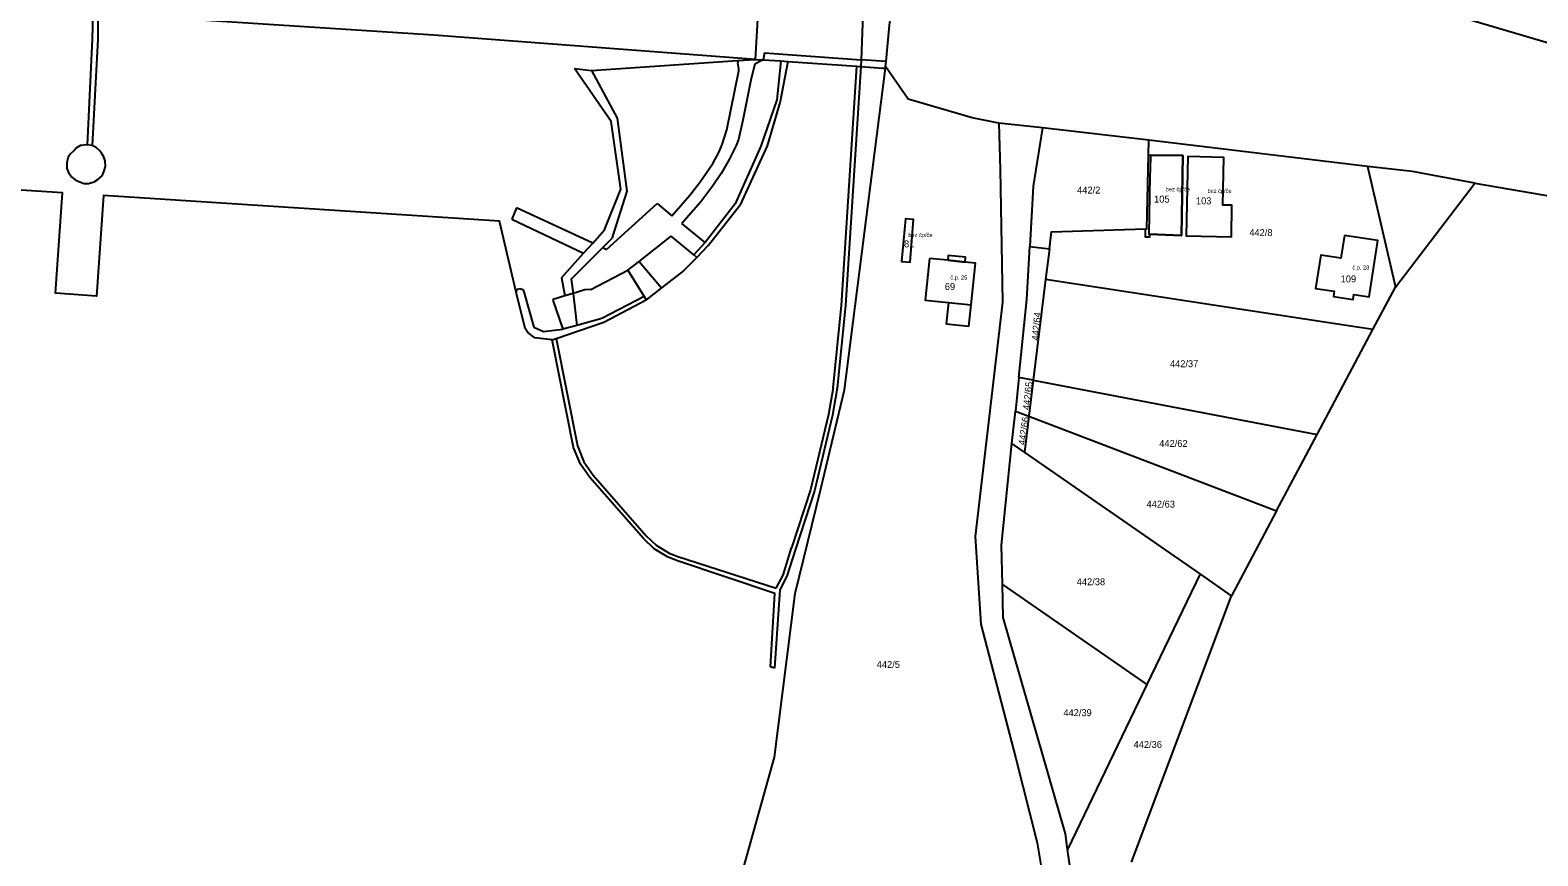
# Model space of a CAD drawing. Extents: x -887272 to -877616, y -1026687 to -1019819.
# Drawn here: x -880439.4 to -880069.6, y -1022775.2 to -1022572.6 of the extents above; entities that cross this region are included whole.
import ezdxf

# ---------------------------------------------------------------- set-up
doc = ezdxf.new("R2010")
doc.units = 0
for name, color, linetype in [('Definiční body', 7, 'Continuous'), ('Hranice parcel', 7, 'Continuous'), ('Parcelní čísla', 7, 'Continuous'), ('Polygon budovy', 7, 'Continuous'), ('Vnitřní kresba', 7, 'Continuous')]:
    doc.layers.add(name, color=color, linetype=linetype)

msp = doc.modelspace()

# ---------------------------------------------------------------- linework, layer by layer
at = {"layer": 'Hranice parcel'}
for p, q in [((-880229.65, -1022581.98), (-880229.6, -1022581.58)), ((-880229.65, -1022581.98), (-880229.6, -1022581.58)), ((-880191.14, -1022596.56), (-880201.85, -1022595.42)), ((-880165.02, -1022599.62), (-880191.14, -1022596.56)), ((-880165.11, -1022603.24), (-880165.02, -1022599.62)), ((-880165.11, -1022603.24), (-880164.68, -1022603.25)), ((-880194.24, -1022625.73), (-880189.45, -1022626.3)), ((-880189.45, -1022626.3), (-880190.36, -1022633.76)), ((-880190.36, -1022633.76), (-880193.39, -1022658.51)), ((-880123.76, -1022671.82), (-880110.08, -1022646.06)), ((-880196.94, -1022657.83), (-880197.79, -1022666.07)), ((-880193.39, -1022658.51), (-880196.94, -1022657.83)), ((-880193.39, -1022658.51), (-880194.47, -1022667.34)), ((-880193.39, -1022658.51), (-880123.76, -1022671.82)), ((-880198.62, -1022674.04), (-880197.79, -1022666.07)), ((-880197.79, -1022666.07), (-880194.47, -1022667.34)), ((-880194.47, -1022667.34), (-880195.55, -1022676.17)), ((-880194.47, -1022667.34), (-880133.71, -1022690.56)), ((-880133.71, -1022690.56), (-880123.76, -1022671.82)), ((-880195.55, -1022676.17), (-880198.62, -1022674.04)), ((-880152.45, -1022706.02), (-880195.55, -1022676.17)), ((-880133.71, -1022690.56), (-880144.75, -1022711.36)), ((-880200.98, -1022708.57), (-880165.51, -1022733.13)), ((-880152.45, -1022706.02), (-880165.51, -1022733.13)), ((-880144.75, -1022711.36), (-880152.45, -1022706.02)), ((-880169.29, -1022776.73), (-880144.75, -1022711.36)), ((-880165.51, -1022733.13), (-880184.98, -1022773.58))]:
    msp.add_line(p, q, dxfattribs=at)
for points in [[(-880166.5, -1022548.2), (-880166.5, -1022563), (-880091.71, -1022568.45), (-880004.96, -1022594.04), (-879942.81, -1022618.93)], [(-880235.23, -1022569.97), (-880235.27, -1022571.01), (-880235.62, -1022579.89), (-880235.68, -1022581.56)], [(-880229.6, -1022581.58), (-880229.48, -1022580.34), (-880228.62, -1022571.37), (-880228.52, -1022570.28)], [(-880229.6, -1022581.58), (-880229.48, -1022580.34), (-880228.62, -1022571.37), (-880228.52, -1022570.28)], [(-880256.89, -1022729.12), (-880257.82, -1022728.77), (-880256.81, -1022710.79), (-880280.91, -1022702.69), (-880283.09, -1022701.83), (-880286.4, -1022699.81), (-880289.01, -1022697.35), (-880302.11, -1022682.39), (-880304.45, -1022679.11), (-880306.13, -1022674.96), (-880311.39, -1022648.61), (-880315.62, -1022648.06), (-880317.36, -1022646.76), (-880318.04, -1022645.79), (-880320.19, -1022636.87), (-880324.31, -1022619.44), (-880421.4, -1022613.18), (-880423.11, -1022637.86), (-880433.18, -1022637.17), (-880431.48, -1022612.53), (-880889.2, -1022583.06)], [(-880275.46, -1022817.7), (-880256.82, -1022750.96), (-880251.78, -1022710.78), (-880245.5, -1022685.14), (-880239.72, -1022660.82), (-880229.65, -1022581.98)], [(-880275.46, -1022817.7), (-880256.82, -1022750.96), (-880251.78, -1022710.78), (-880245.5, -1022685.14), (-880239.72, -1022660.82), (-880229.65, -1022581.98)], [(-880235.68, -1022581.56), (-880239.44, -1022640.2), (-880241.51, -1022660.47), (-880242.64, -1022667.04), (-880247.06, -1022685.59), (-880251.71, -1022699.93), (-880253.82, -1022706.59)], [(-880201.85, -1022595.42), (-880208.37, -1022594.15), (-880224.11, -1022589.52), (-880229.6, -1022581.58)], [(-880201.85, -1022595.42), (-880201.5, -1022606.82), (-880200.91, -1022639.32), (-880207.63, -1022696.81), (-880206.25, -1022718.31), (-880197.77, -1022750.95), (-880192.42, -1022771.99), (-880190.9, -1022781.26)], [(-880191.14, -1022596.56), (-880193.43, -1022610.91), (-880194.24, -1022625.73)], [(-880085.09, -1022610.19), (-880100.38, -1022607.29), (-880111.43, -1022606.07), (-880165.02, -1022599.62)], [(-880165.85, -1022621.37), (-880165.55, -1022621.36), (-880165.11, -1022603.24)], [(-880164.68, -1022603.25), (-880156.7, -1022603.38), (-880157.02, -1022623.01), (-880164.89, -1022622.7)], [(-880146.89, -1022615.53), (-880146.62, -1022603.84), (-880155.47, -1022603.64), (-880155.91, -1022623.1), (-880144.81, -1022623.36), (-880144.66, -1022615.58), (-880146.89, -1022615.53)], [(-880110.08, -1022646.06), (-880104.57, -1022635.67), (-880085.09, -1022610.19)], [(-880085.09, -1022610.19), (-880006.95, -1022623.58), (-879948.33, -1022639.86), (-879895.51, -1022661.38), (-879854.76, -1022684.53)], [(-880223.61, -1022629.54), (-880222.73, -1022619.05), (-880224.76, -1022618.92), (-880225.68, -1022629.39), (-880223.61, -1022629.54)], [(-880189.45, -1022626.3), (-880188.93, -1022622.11), (-880165.85, -1022621.37)], [(-880164.89, -1022622.7), (-880164.92, -1022623.44), (-880165.89, -1022623.4), (-880165.85, -1022621.37)], [(-880117.08, -1022623.02), (-880117.95, -1022628.55), (-880122.9, -1022627.78), (-880124.2, -1022636.02), (-880119.61, -1022636.65), (-880119.79, -1022637.93), (-880114.95, -1022638.69), (-880114.75, -1022637.47), (-880111.03, -1022638.06), (-880108.92, -1022624.26), (-880117.08, -1022623.02)], [(-880218.86, -1022628.64), (-880219.91, -1022638.86), (-880214.19, -1022639.45), (-880214.73, -1022644.64), (-880209.18, -1022645.22), (-880208.64, -1022640.02), (-880207.57, -1022629.75), (-880210.12, -1022629.5), (-880210, -1022628.28), (-880214.26, -1022627.86), (-880214.38, -1022629.08), (-880218.86, -1022628.64)], [(-880196.94, -1022657.83), (-880194.95, -1022638.71), (-880194.24, -1022625.73)], [(-880110.08, -1022646.06), (-880119.83, -1022644.57), (-880190.36, -1022633.76)], [(-880200.98, -1022708.57), (-880201.21, -1022698.97), (-880198.62, -1022674.04)], [(-880253.82, -1022706.59), (-880255.54, -1022709.92), (-880256.89, -1022729.12)], [(-880184.98, -1022773.58), (-880185.52, -1022769.75), (-880200.78, -1022716.69), (-880200.98, -1022708.57)], [(-880183.96, -1022798.18), (-880184.04, -1022780.28), (-880184.98, -1022773.58)]]:
    msp.add_lwpolyline(points, dxfattribs=at)
at = {"layer": 'Polygon budovy'}
for points in [[(-880164.68, -1022603.25), (-880164.73, -1022606.78), (-880164.82, -1022608.39), (-880165.02, -1022622.7), (-880164.89, -1022622.7), (-880157.02, -1022623.01), (-880156.7, -1022603.38)], [(-880146.62, -1022603.84), (-880155.47, -1022603.64), (-880155.91, -1022623.1), (-880144.81, -1022623.36), (-880144.66, -1022615.58), (-880146.89, -1022615.53)], [(-880225.68, -1022629.39), (-880223.61, -1022629.54), (-880222.73, -1022619.05), (-880224.76, -1022618.92)], [(-880117.08, -1022623.02), (-880117.95, -1022628.55), (-880122.9, -1022627.78), (-880124.2, -1022636.02), (-880119.61, -1022636.65), (-880119.79, -1022637.93), (-880114.95, -1022638.69), (-880114.75, -1022637.47), (-880111.03, -1022638.06), (-880108.92, -1022624.26)], [(-880218.86, -1022628.64), (-880219.91, -1022638.86), (-880214.19, -1022639.45), (-880208.64, -1022640.02), (-880207.57, -1022629.75), (-880210.12, -1022629.5), (-880214.38, -1022629.08)]]:
    msp.add_lwpolyline(points, close=True, dxfattribs=at)
at = {"layer": 'Vnitřní kresba'}
for p, q in [((-880424, -1022568.5), (-880424.22, -1022574.8)), ((-880422.78, -1022568.56), (-880422.84, -1022574.82)), ((-880340.44, -1022573.88), (-880422.78, -1022568.56)), ((-880260.96, -1022568.52), (-880261.58, -1022579.8)), ((-880424.22, -1022574.8), (-880425.46, -1022600.76)), ((-880422.84, -1022574.82), (-880424.16, -1022600.94)), ((-880261.58, -1022579.8), (-880340.44, -1022573.88)), ((-880265.92, -1022580.11), (-880261.58, -1022579.8)), ((-880261.58, -1022579.8), (-880259.64, -1022579.92)), ((-880259.32, -1022578.16), (-880259.64, -1022579.92)), ((-880259.32, -1022578.16), (-880235.62, -1022579.89)), ((-880296.9, -1022595.02), (-880305.88, -1022582.02)), ((-880305.88, -1022582.02), (-880301.72, -1022582.52)), ((-880301.72, -1022582.52), (-880265.92, -1022580.11)), ((-880301.72, -1022582.52), (-880295.46, -1022594.18)), ((-880268.55, -1022597.08), (-880265.63, -1022582.63)), ((-880265.92, -1022580.11), (-880265.83, -1022580.66)), ((-880265.6, -1022582.14), (-880265.83, -1022580.66)), ((-880265.63, -1022582.63), (-880265.6, -1022582.14)), ((-880261.66, -1022580.98), (-880262.54, -1022584.5)), ((-880260.16, -1022580.19), (-880261.66, -1022580.98)), ((-880259.64, -1022579.92), (-880260.16, -1022580.19)), ((-880259.64, -1022579.92), (-880255.34, -1022580.18)), ((-880255.34, -1022580.18), (-880256.3, -1022589.68)), ((-880253.59, -1022580.3), (-880255.5, -1022590.14)), ((-880255.34, -1022580.18), (-880253.59, -1022580.3)), ((-880253.59, -1022580.3), (-880236.68, -1022581.5)), ((-880240.44, -1022640.14), (-880236.68, -1022581.5)), ((-880236.68, -1022581.5), (-880236.1, -1022581.54)), ((-880236.1, -1022581.54), (-880235.68, -1022581.56)), ((-880235.68, -1022581.56), (-880230.31, -1022581.93)), ((-880229.48, -1022580.34), (-880235.62, -1022579.89)), ((-880230.31, -1022581.93), (-880229.65, -1022581.98)), ((-880262.54, -1022584.5), (-880264.65, -1022594.7)), ((-880256.3, -1022589.68), (-880260.22, -1022601.12)), ((-880255.5, -1022590.14), (-880258.68, -1022600.96)), ((-880295.46, -1022594.18), (-880293.04, -1022612.08)), ((-880294.58, -1022611.66), (-880296.9, -1022595.02)), ((-880269.69, -1022600.68), (-880268.55, -1022597.08)), ((-880264.65, -1022594.7), (-880265.68, -1022599.47)), ((-880428.04, -1022601.52), (-880428.62, -1022602.12)), ((-880427.06, -1022600.92), (-880428.04, -1022601.52)), ((-880425.46, -1022600.76), (-880427.06, -1022600.92)), ((-880424.16, -1022600.94), (-880425.46, -1022600.76)), ((-880423.2, -1022601.44), (-880424.16, -1022600.94)), ((-880422.42, -1022602.14), (-880423.2, -1022601.44)), ((-880270.53, -1022602.6), (-880269.69, -1022600.68)), ((-880266.25, -1022600.93), (-880267.95, -1022604.37)), ((-880260.22, -1022601.12), (-880266.5, -1022615.24)), ((-880265.68, -1022599.47), (-880266.25, -1022600.93)), ((-880258.68, -1022600.96), (-880265.28, -1022615.5)), ((-880430.1, -1022603.78), (-880430.42, -1022605.08)), ((-880430.42, -1022605.08), (-880430.38, -1022606.52)), ((-880429.5, -1022602.94), (-880430.1, -1022603.78)), ((-880428.62, -1022602.12), (-880429.5, -1022602.94)), ((-880421.92, -1022602.8), (-880422.42, -1022602.14)), ((-880421.34, -1022603.72), (-880421.92, -1022602.8)), ((-880421.02, -1022604.7), (-880421.34, -1022603.72)), ((-880420.92, -1022606.04), (-880421.02, -1022604.7)), ((-880275.07, -1022609.82), (-880271.97, -1022605.32)), ((-880271.97, -1022605.32), (-880270.53, -1022602.6)), ((-880267.95, -1022604.37), (-880269.92, -1022607.76)), ((-880164.68, -1022603.25), (-880164.73, -1022606.78)), ((-880430.38, -1022606.52), (-880430, -1022607.52)), ((-880430, -1022607.52), (-880429.24, -1022608.64)), ((-880429.24, -1022608.64), (-880428.36, -1022609.32)), ((-880428.36, -1022609.32), (-880427.06, -1022609.94)), ((-880423.68, -1022609.8), (-880422.78, -1022609.24)), ((-880422.78, -1022609.24), (-880421.76, -1022608.38)), ((-880421.76, -1022608.38), (-880421.3, -1022607.38)), ((-880421.3, -1022607.38), (-880420.92, -1022606.04)), ((-880269.92, -1022607.76), (-880271.99, -1022610.85)), ((-880164.82, -1022608.39), (-880165.02, -1022622.7)), ((-880164.73, -1022606.78), (-880164.82, -1022608.39)), ((-880111.43, -1022606.07), (-880104.57, -1022635.67)), ((-880427.06, -1022609.94), (-880426.18, -1022610.26)), ((-880426.18, -1022610.26), (-880425.12, -1022610.26)), ((-880425.12, -1022610.26), (-880423.68, -1022609.8)), ((-880298.58, -1022621.64), (-880294.58, -1022611.66)), ((-880293.04, -1022612.08), (-880296.71, -1022623.71)), ((-880282.04, -1022618.16), (-880277.59, -1022613.1)), ((-880277.59, -1022613.1), (-880275.07, -1022609.82)), ((-880271.99, -1022610.85), (-880274.95, -1022614.76)), ((-880320.09, -1022616.22), (-880321.26, -1022618.95)), ((-880301.44, -1022624.84), (-880320.09, -1022616.22)), ((-880298.02, -1022626.42), (-880285.64, -1022615.16)), ((-880285.64, -1022615.16), (-880282.04, -1022618.16)), ((-880274.95, -1022614.76), (-880279.57, -1022620.06)), ((-880266.5, -1022615.24), (-880273.84, -1022624.71)), ((-880273.06, -1022625.34), (-880265.28, -1022615.5)), ((-880321.26, -1022618.95), (-880303.68, -1022627.34)), ((-880273.84, -1022624.71), (-880279.57, -1022620.06)), ((-880301.44, -1022624.84), (-880298.58, -1022621.64)), ((-880298.99, -1022625.97), (-880296.71, -1022623.71)), ((-880290.03, -1022629.41), (-880282.16, -1022623.14)), ((-880276.68, -1022627.73), (-880282.16, -1022623.14)), ((-880165.02, -1022622.7), (-880164.89, -1022622.7)), ((-880309.06, -1022633.34), (-880303.68, -1022627.34)), ((-880303.68, -1022627.34), (-880301.44, -1022624.84)), ((-880301.45, -1022628.4), (-880298.99, -1022625.97)), ((-880298.99, -1022625.97), (-880298.02, -1022626.42)), ((-880276.68, -1022627.73), (-880273.84, -1022624.71)), ((-880275.91, -1022628.37), (-880276.68, -1022627.73)), ((-880273.26, -1022625.6), (-880275.91, -1022628.37)), ((-880273.06, -1022625.34), (-880273.26, -1022625.6)), ((-880306.69, -1022633.69), (-880304.04, -1022631.01)), ((-880304.04, -1022631.01), (-880301.45, -1022628.4)), ((-880301.92, -1022636.26), (-880292.85, -1022631.5)), ((-880292.85, -1022631.5), (-880290.03, -1022629.41)), ((-880292.85, -1022631.5), (-880288.84, -1022637.95)), ((-880290.03, -1022629.41), (-880284.55, -1022635.82)), ((-880275.91, -1022628.37), (-880279.21, -1022631.65)), ((-880214.38, -1022629.08), (-880210.12, -1022629.5)), ((-880309.06, -1022633.34), (-880308.26, -1022637.82)), ((-880306.69, -1022633.69), (-880306.27, -1022637.21)), ((-880279.21, -1022631.65), (-880284.55, -1022635.82)), ((-880320.08, -1022636.27), (-880320.19, -1022636.87)), ((-880319.05, -1022636.08), (-880320.08, -1022636.27)), ((-880319.05, -1022636.08), (-880318.59, -1022636.27)), ((-880318.59, -1022636.27), (-880318.33, -1022636.83)), ((-880318.33, -1022636.83), (-880315.9, -1022645.45)), ((-880311.2, -1022638.85), (-880311.12, -1022638.68)), ((-880311.2, -1022638.85), (-880308.76, -1022645.98)), ((-880308.26, -1022637.82), (-880311.12, -1022638.68)), ((-880306.27, -1022637.21), (-880308.26, -1022637.82)), ((-880303.41, -1022636.35), (-880306.27, -1022637.21)), ((-880306.27, -1022637.21), (-880305.34, -1022645.04)), ((-880301.92, -1022636.26), (-880303.41, -1022636.35)), ((-880288.84, -1022637.95), (-880299.19, -1022643.35)), ((-880298.73, -1022644.24), (-880288.33, -1022638.77)), ((-880288.84, -1022637.95), (-880288.33, -1022638.77)), ((-880284.55, -1022635.82), (-880288.33, -1022638.77)), ((-880242.5, -1022660.37), (-880240.44, -1022640.14)), ((-880214.19, -1022639.45), (-880208.64, -1022640.02)), ((-880315.9, -1022645.45), (-880313.51, -1022646.54)), ((-880313.51, -1022646.54), (-880308.76, -1022645.98)), ((-880310.44, -1022648.28), (-880298.73, -1022644.24)), ((-880305.34, -1022645.04), (-880308.76, -1022645.98)), ((-880299.19, -1022643.35), (-880305.34, -1022645.04)), ((-880311.39, -1022648.61), (-880310.44, -1022648.28)), ((-880310.44, -1022648.28), (-880305.2, -1022674.59)), ((-880242.5, -1022660.37), (-880243.63, -1022666.87)), ((-880243.63, -1022666.87), (-880248.03, -1022685.36)), ((-880305.2, -1022674.59), (-880303.64, -1022678.53)), ((-880303.64, -1022678.53), (-880301.3, -1022681.81)), ((-880301.3, -1022681.81), (-880288.32, -1022696.62)), ((-880248.03, -1022685.36), (-880252.66, -1022699.62)), ((-880288.32, -1022696.62), (-880285.88, -1022698.96)), ((-880285.88, -1022698.96), (-880282.72, -1022700.9)), ((-880282.72, -1022700.9), (-880280.59, -1022701.74)), ((-880280.59, -1022701.74), (-880256.46, -1022709.48)), ((-880254.77, -1022706.29), (-880252.66, -1022699.62)), ((-880256.46, -1022709.48), (-880254.77, -1022706.29))]:
    msp.add_line(p, q, dxfattribs=at)

# ---------------------------------------------------------------- texts
at = {"layer": 'Definiční body'}
for s, p in [('bez čp/če', (-880160.88, -1022612.15)), ('bez čp/če', (-880150.66, -1022612.54)), ('bez čp/če', (-880224.03, -1022623.36)), ('č.p. 28', (-880115.12, -1022631.35)), ('č.p. 25', (-880213.74, -1022633.8))]:
    msp.add_text(s, height=1, dxfattribs=at).set_placement(p)
at = {"layer": 'Parcelní čísla'}
for s, p in [('442/2', (-880182.64, -1022612.7)), ('105', (-880163.76, -1022614.92)), ('103', (-880153.5, -1022615.34)), ('81', (-880225.09, -1022625.91)), ('442/8', (-880140.41, -1022623.13)), ('69', (-880215.09, -1022636.36)), ('109', (-880118.01, -1022634.49)), ('442/37', (-880159.87, -1022655.29)), ('442/62', (-880162.5, -1022674.85)), ('442/63', (-880165.6, -1022689.74)), ('442/38', (-880182.73, -1022708.77)), ('442/5', (-880231.78, -1022729.05)), ('442/39', (-880186.01, -1022740.89)), ('442/36', (-880168.79, -1022748.68))]:
    msp.add_text(s, height=1.7, dxfattribs=at).set_placement(p)
for s, rotation, p in [('442/64', 85, (-880192.09, -1022648.83)), ('442/65', 84, (-880194.29, -1022665.87)), ('442/66', 82, (-880195.39, -1022674.48))]:
    msp.add_text(s, height=1.7, rotation=rotation, dxfattribs=at).set_placement(p)

doc.saveas('drawing.dxf')
